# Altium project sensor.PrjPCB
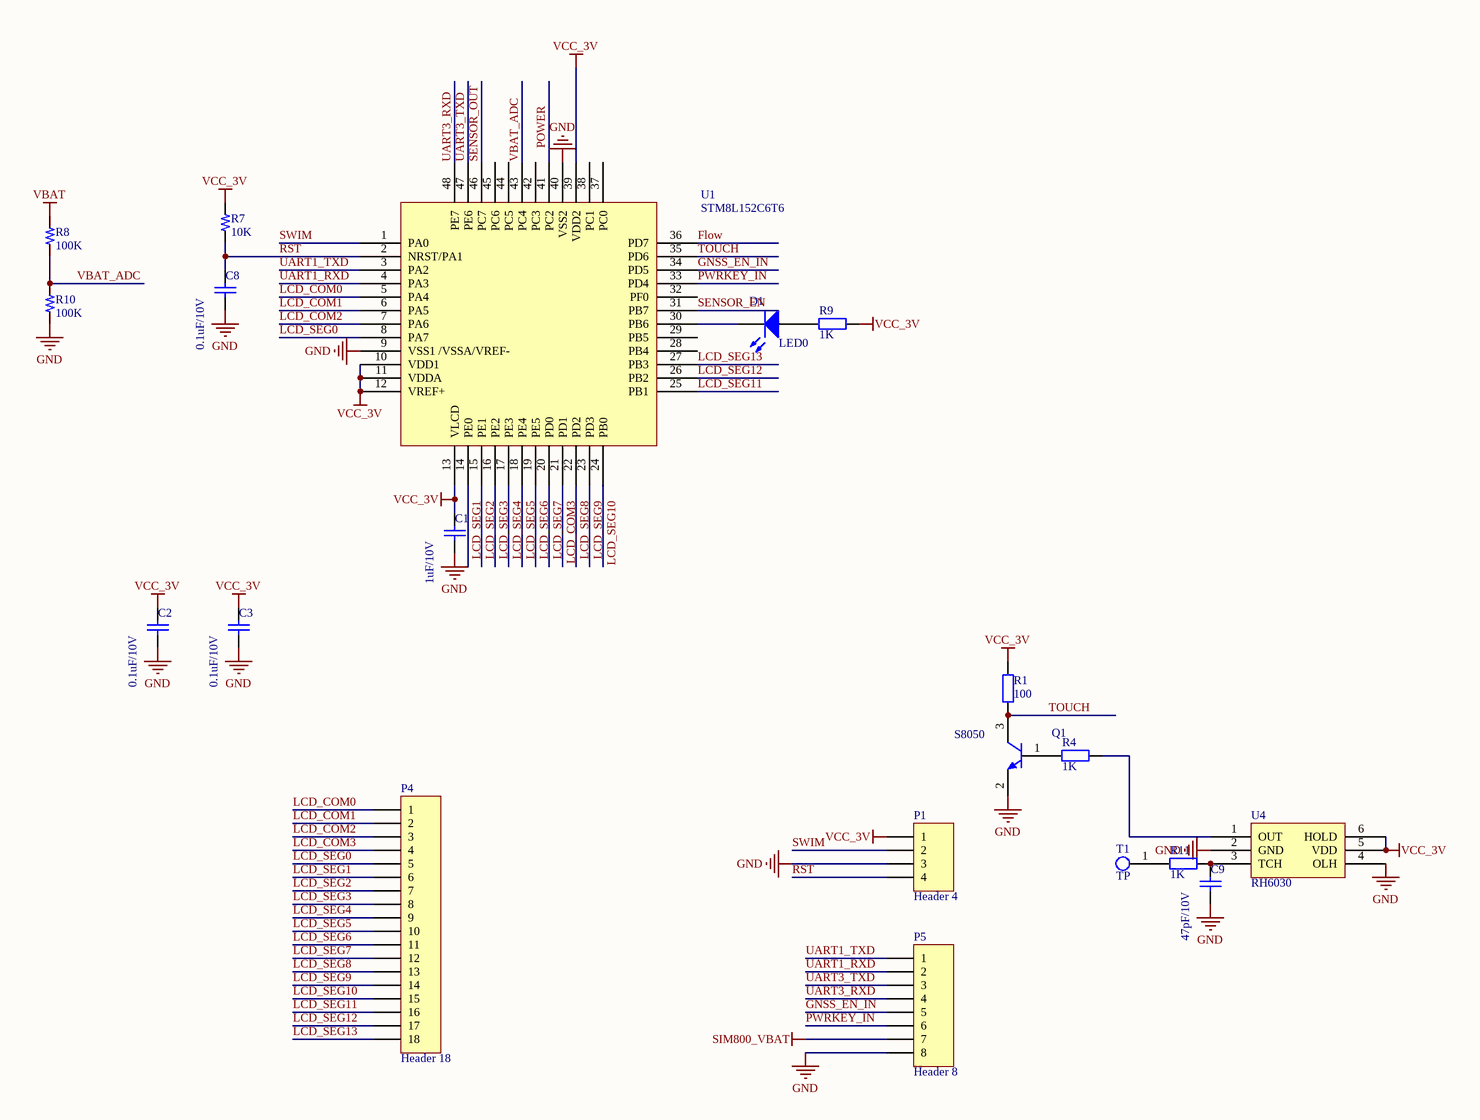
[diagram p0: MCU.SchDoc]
2 sheets, 62 parts. Net scope: global (net labels, ports and power ports of the same name join across sheets).
Board file: PCB1.PcbDoc
Sheets:
  MCU.SchDoc
  power.SchDoc

## Sheet MCU.SchDoc
size A3

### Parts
C1  1uF/10V  [0603C]
C2  0.1uF/10V  [0603C]
C3  0.1uF/10V  [0603C]
C8  0.1uF/10V  [0603C]
C9  47pF/10V  [0603C]
D1  LED0  [0603LED]
P1  Header 4  [HDR1X4]
P4  Header 18  [lcd]
P5  Header 8  [HDR1X8]
Q1  S8050  [SOT23-3]
R1  100  [0603R]
R4  1K  [0603R]
R7  10K  [0603R]
R8  100K  [0603R]
R9  1K  [0603R]
R10  100K  [0603R]
R11  1K  [0603R]
T1  TP  [TOUCH-PAD]
U1  STM8L152C6T6  [TQFP-48]
U4  RH6030  [SOT-23-6]

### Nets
GND: C1.2 C2.2 C3.2 C8.2 C9.2 P1.3 P5.8 Q1.2(E) R10.1 U1.9(VSS1_/VSSA/VREF-) U1.40(VSS2) U4.2(GND) U4.4(OLH)
SIM800_VBAT: P5.7 R8.2  [also labelled VBAT]
VCC_3V: C1.1 C2.1 C3.1 P1.1 R1.1 R7.2 R9.1 U1.10(VDD1) U1.11(VDDA) U1.12(VREF+) U1.13(VLCD) U1.39(VDD2) U4.5(VDD) U4.6(HOLD)
Flow: U1.36(PD7)
GNSS_EN_IN: P5.5 U1.34(PD5)
LCD_COM0: P4.1 U1.5(PA4)
LCD_COM1: P4.2 U1.6(PA5)
LCD_COM2: P4.3 U1.7(PA6)
LCD_COM3: P4.4 U1.21(PD1)
LCD_SEG0: P4.5 U1.8(PA7)
LCD_SEG1: P4.6 U1.14(PE0)
LCD_SEG2: P4.7 U1.15(PE1)
LCD_SEG3: P4.8 U1.16(PE2)
LCD_SEG4: P4.9 U1.17(PE3)
LCD_SEG5: P4.10 U1.18(PE4)
LCD_SEG6: P4.11 U1.19(PE5)
LCD_SEG7: P4.12 U1.20(PD0)
LCD_SEG8: P4.13 U1.22(PD2)
LCD_SEG9: P4.14 U1.23(PD3)
LCD_SEG10: P4.15 U1.24(PB0)
LCD_SEG11: P4.16 U1.25(PB1)
LCD_SEG12: P4.17 U1.26(PB2)
LCD_SEG13: P4.18 U1.27(PB3)
POWER: U1.41(PC2)
PWRKEY_IN: P5.6 U1.33(PD4)
RST: C8.1 P1.4 R7.1 U1.2(NRST/PA1)
SENSOR_EN: U1.31(PB7)
SENSOR_OUT: U1.46(PC7)
SWIM: P1.2 U1.1(PA0)
TOUCH: Q1.3(C) R1.2 U1.35(PD6)
UART1_RXD: P5.2 U1.4(PA3)
UART1_TXD: P5.1 U1.3(PA2)
UART3_RXD: P5.4 U1.48(PE7)
UART3_TXD: P5.3 U1.47(PE6)
VBAT_ADC: R8.1 R10.2 U1.43(PC4)
NetC9_1: C9.1 R11.1 U4.3(TCH)
NetD1_1: D1.1(A) R9.2
NetD1_2: D1.2(K) U1.30(PB6)
NetQ1_1: Q1.1(B) R4.2
NetR4_1: R4.1 U4.1(OUT)
NetR11_2: R11.2 T1.1

Not connected (* = marked no-connect by the designer): U1 28(PB4) 29(PB5) 32(PF0) 37(PC0) 38(PC1) 42(PC3) 44(PC5) 45(PC6)

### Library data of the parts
C1-C3 C8 C9 = Cap: Capacitor; Value: 104
D1 = LED0: Typical INFRARED GaAs LED
P1 = Header 4: Header, 4-Pin
P4 = Header 18: Header, 18-Pin
P5 = Header 8: Header, 8-Pin
Q1 = NPN
R1 = Res2: Resistor; Value: 1K
R4 R9 R11 = Res2: Resistor
R7 R8 R10 = R

## Sheet power.SchDoc
size A3
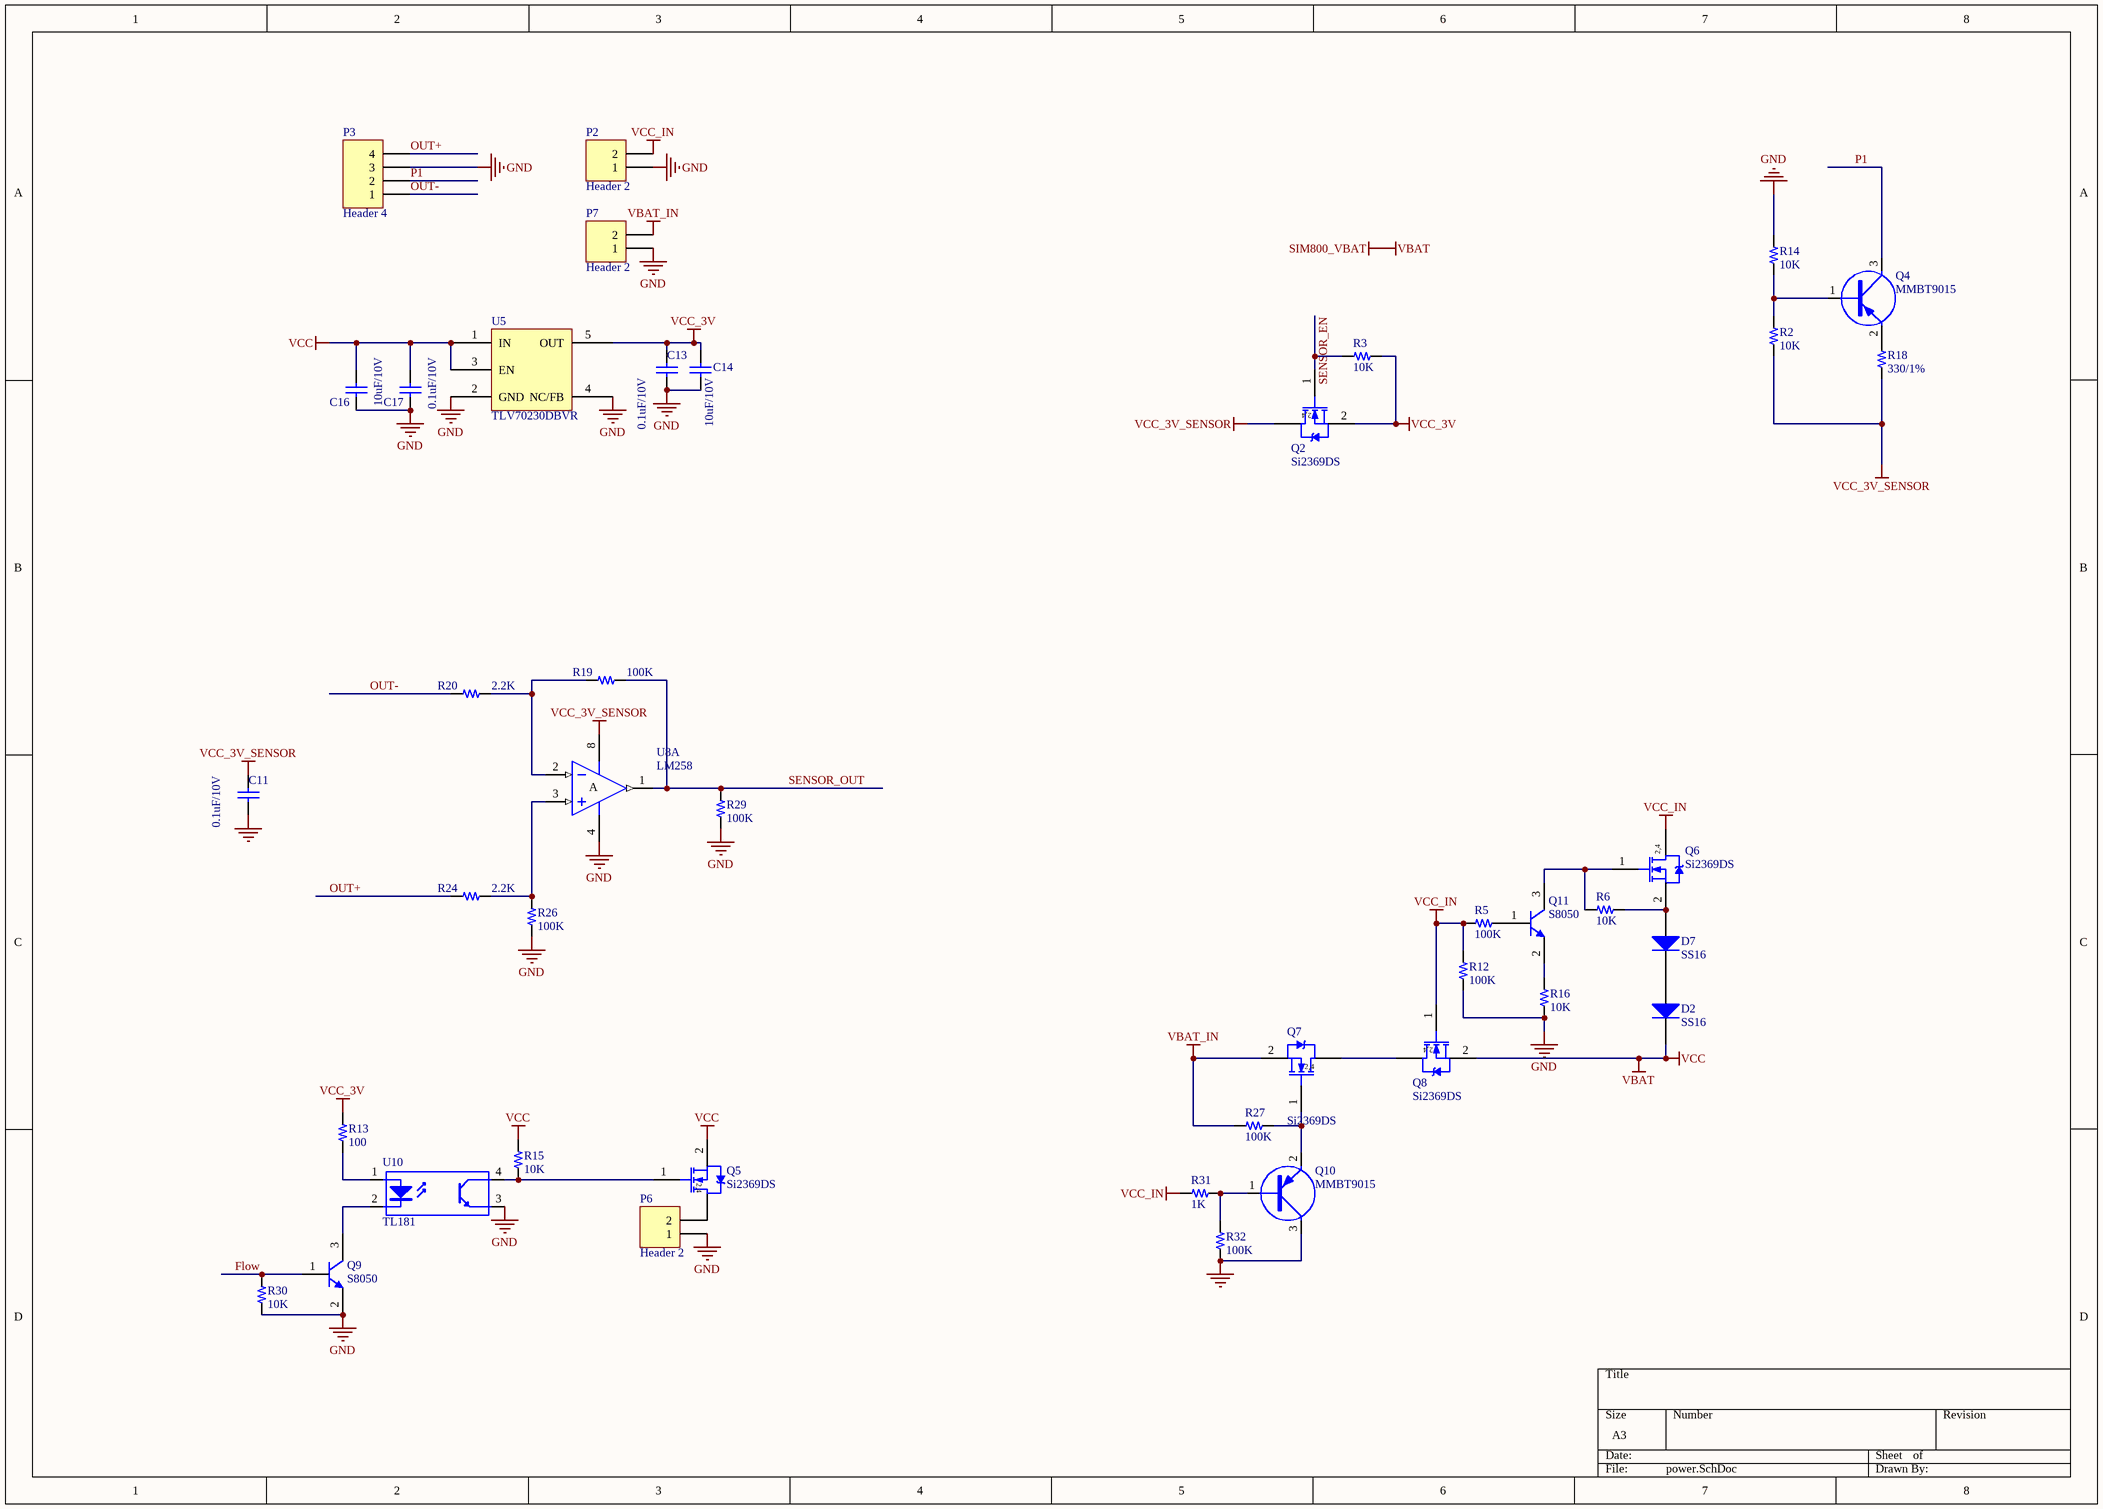
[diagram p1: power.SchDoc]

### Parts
C11  0.1uF/10V  [0603C]
C13  0.1uF/10V  [0603C]
C14  10uF/10V  [0603C]
C16  10uF/10V  [0603C]
C17  0.1uF/10V  [0603C]
D2  SS16  [SMA]
D7  SS16  [SMA]
P2  Header 2  [2X2.54MM]
P3  Header 4  [HDR1X4]
P6  Header 2  [HDR1X2]
P7  Header 2  [2X2.54MM]
Q2  Si2369DS  [SOT23-3]
Q4  MMBT9015  [SOT23-3]
Q5  Si2369DS  [SOT23-3]
Q6  Si2369DS  [SOT23-3]
Q7  Si2369DS  [SOT23-3]
Q8  Si2369DS  [SOT23-3]
Q9  S8050  [SOT23-3]
Q10  MMBT9015  [SOT23-3]
Q11  S8050  [SOT23-3]
R2  10K  [0603R]
R3  10K  [0603R]
R5  100K  [0603R]
R6  10K  [0603R]
R12  100K  [0603R]
R13  100  [0603R]
R14  10K  [0603R]
R15  10K  [0603R]
R16  10K  [0603R]
R18  330/1%  [0603R]
R19  100K  [0603R]
R20  2.2K  [0603R]
R24  2.2K  [0603R]
R26  100K  [0603R]
R27  100K  [0603R]
R29  100K  [0603R]
R30  10K  [0603R]
R31  1K  [0603R]
R32  100K  [0603R]
U5  TLV70230DBVR  [SOT23-5(DBV)]
U8  LM258  [so-8]  (part A of 2)
U10  TL181  [DIP-4]

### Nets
GND: C11.2 C13.2 C14.1 C16.1 C17.2 P2.1 P3.3 P6.1 P7.1 Q9.2(E) Q10.3(C) R12.2 R14.2 R16.1 R26.1 R29.1 R30.1 R32.1 U5.2(GND) U5.4(NC/FB) U8.4(V-) U10.3(E)
SIM800_VBAT: C16.2 C17.1 D2.2(K) Q5.2(S) Q8.2(S) R15.2 U5.1(IN) U5.3(EN)  [also labelled VBAT, VCC]
VBAT_IN: P7.2 Q7.2(S) R27.1
VCC_3V: C13.1 C14.2 Q2.2(S) R3.1 R13.2 U5.5(OUT)
VCC_3V_SENSOR: C11.1 Q2.3(D) R2.1 R18.1 U8.8(V+)
VCC_IN: P2.2 Q6.3(D) Q8.1(G) R5.1 R12.1 R31.1
Flow: Q9.1(B) R30.2
OUT+: P3.4 R24.1
OUT-: P3.1 R20.1
P1: P3.2 Q4.3(C)
SENSOR_EN: Q2.1(G) R3.2
SENSOR_OUT: R19.2 R29.2 U8.1(OUT)
NetD2_1: D2.1(A) D7.2(K)
NetD7_1: D7.1(A) Q6.2(S) R6.1
NetP6_2: P6.2 Q5.3(D)
NetQ4_1: Q4.1(B) R2.2 R14.1
NetQ4_2: Q4.2(E) R18.2
NetQ5_1: Q5.1(G) R15.1 U10.4(C)
NetQ6_1: Q6.1(G) Q11.3(C) R6.2
NetQ7_1: Q7.1(G) Q10.2(E) R27.2
NetQ7_3: Q7.3(D) Q8.3(D)
NetQ9_3: Q9.3(C) U10.2(K)
NetQ10_1: Q10.1(B) R31.2 R32.2
NetQ11_1: Q11.1(B) R5.2
NetQ11_2: Q11.2(E) R16.2
NetR13_1: R13.1 U10.1(A)
NetR19_1: R19.1 R20.2 U8.2(IN-)
NetR24_2: R24.2 R26.2 U8.3(IN+)

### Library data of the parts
C11 C13 C17 = Cap: Capacitor; Value: 104
C14 = Cap: Capacitor
C16 = Cap: Capacitor; Value: 106/50V
D2 D7 = Diode 1N4148: High Conductance Fast Diode
P2 P6 P7 = Header 2: Header, 2-Pin
P3 = Header 4: Header, 4-Pin
Q2 Q5-Q8 = BUK92150-55A
Q4 Q10 = PNP
Q9 Q11 = NPN
R2 R3 R5 R6 R12-R16 R18-R20 R24 R26 R27 R29-R32 = R
U10 = Optoisolator1: 4-Pin Phototransistor Optocoupler

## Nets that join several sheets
GND: MCU (13 pins), power (22 pins)
SIM800_VBAT: MCU (P5.7 R8.2), power (8 pins)
VCC_3V: MCU (14 pins), power (6 pins)
Flow: MCU (U1.36), power (Q9.1 R30.2)
SENSOR_EN: MCU (U1.31), power (Q2.1 R3.2)
SENSOR_OUT: MCU (U1.46), power (R19.2 R29.2 U8.1)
